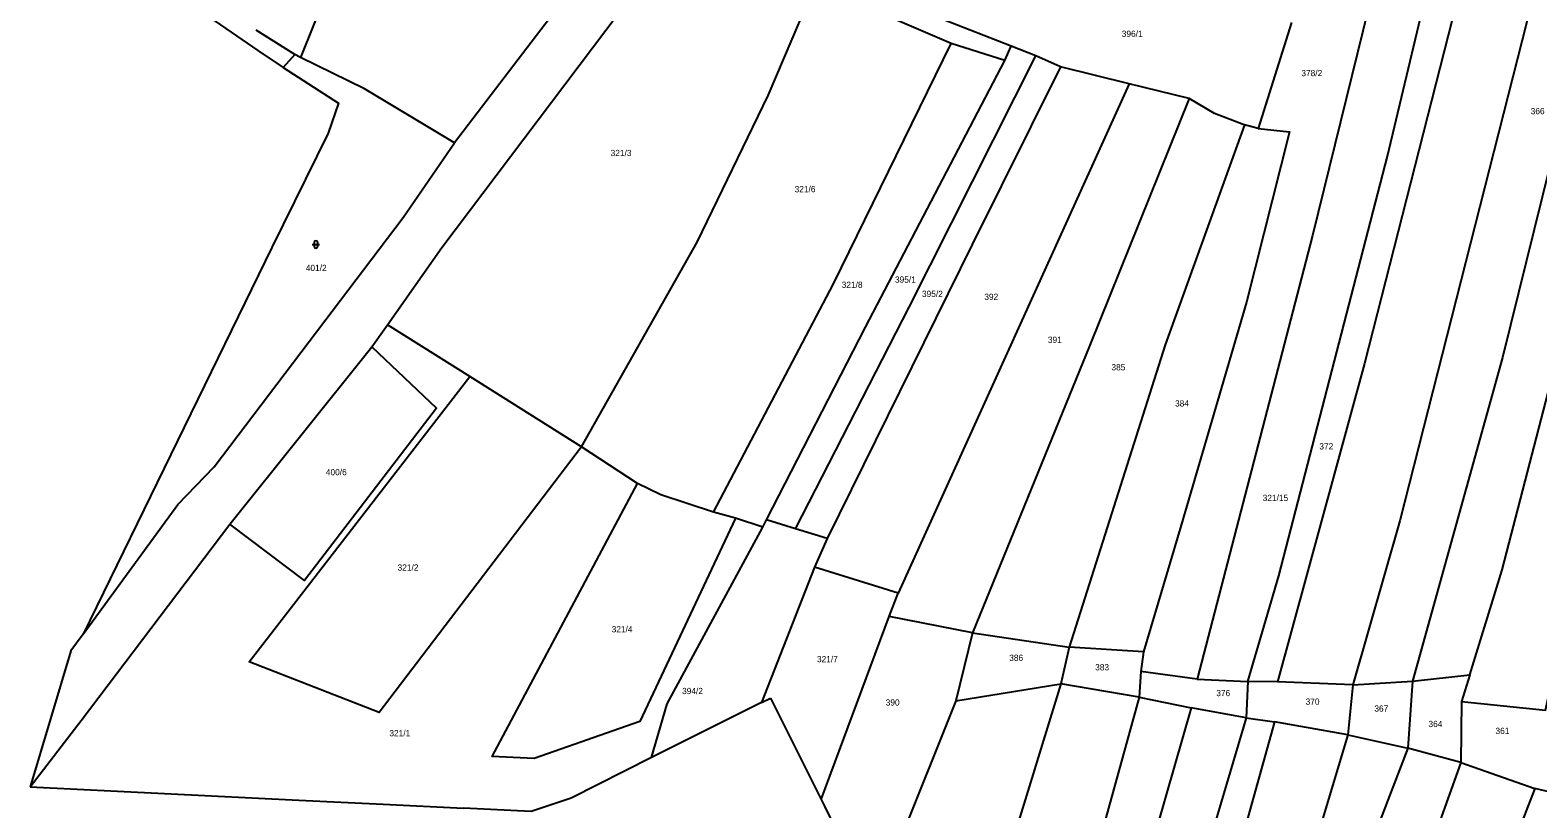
# Model space of a CAD drawing. Extents: x -746176 to -739709, y -1128407 to -1124482.
# Drawn here: x -744013.6 to -743602.7, y -1127772.3 to -1127560 of the extents above; entities that cross this region are included whole.
import ezdxf

# ---------------------------------------------------------------- set-up
doc = ezdxf.new("R2010")
doc.units = 0
for name, color, linetype in [('Vrstva 33', 7, 'Continuous'), ('Vrstva 42', 7, 'Continuous'), ('Vrstva 44', 7, 'Continuous')]:
    doc.layers.add(name, color=color, linetype=linetype)

msp = doc.modelspace()

# ---------------------------------------------------------------- linework, layer by layer
at = {"layer": 'Vrstva 33'}
for p, q in [((-743762.59, -1127563.64), (-743799.59, -1127547.73)), ((-743746.22, -1127564.41), (-743764.87, -1127557.13)), ((-743941.47, -1127566.69), (-743952.02, -1127560)), ((-743669.86, -1127557.99), (-743678.91, -1127586.83)), ((-743951.49, -1127565.55), (-743944.64, -1127570.24)), ((-743747.9, -1127568.32), (-743762.59, -1127563.64)), ((-743747.9, -1127568.32), (-743746.22, -1127564.41)), ((-743739.51, -1127567.07), (-743746.22, -1127564.41)), ((-743941.47, -1127566.69), (-743944.64, -1127570.24)), ((-743939.9, -1127567.46), (-743941.47, -1127566.69)), ((-743732.8, -1127570.06), (-743739.51, -1127567.07)), ((-743714.07, -1127574.65), (-743732.8, -1127570.06)), ((-743714.07, -1127574.65), (-743777.04, -1127713.53)), ((-743697.73, -1127578.65), (-743714.07, -1127574.65)), ((-743678.91, -1127586.83), (-743682.66, -1127585.84)), ((-743947.67, -1127619.31), (-743999.16, -1127724.64)), ((-743920.46, -1127646.39), (-743916.19, -1127640.32)), ((-743893.74, -1127654.46), (-743916.19, -1127640.32)), ((-743959.16, -1127694.66), (-743920.46, -1127646.39)), ((-743863.3, -1127673.64), (-743893.74, -1127654.46)), ((-743848.02, -1127683.56), (-743863.3, -1127673.64)), ((-743821.37, -1127693.07), (-743827.35, -1127691.38)), ((-743813.91, -1127695.5), (-743821.37, -1127693.07)), ((-743813.91, -1127695.5), (-743812.88, -1127693.5)), ((-743804.98, -1127695.97), (-743812.88, -1127693.5)), ((-743796.4, -1127698.58), (-743804.98, -1127695.97)), ((-743796.4, -1127698.58), (-743799.83, -1127706.36)), ((-743799.83, -1127706.36), (-743814.29, -1127743.33)), ((-743777.04, -1127713.53), (-743799.83, -1127706.36)), ((-743779.45, -1127719.83), (-743777.04, -1127713.53)), ((-743798.01, -1127769.73), (-743779.45, -1127719.83)), ((-743756.8, -1127724.26), (-743779.45, -1127719.83)), ((-743999.16, -1127724.64), (-744000.94, -1127727.08)), ((-743756.8, -1127724.26), (-743761.26, -1127742.79)), ((-743756.8, -1127724.26), (-743730.37, -1127728.24)), ((-744002.49, -1127729.2), (-744013.58, -1127766.31)), ((-744000.94, -1127727.08), (-744002.49, -1127729.2)), ((-743730.37, -1127728.24), (-743732.64, -1127738.2)), ((-743710.14, -1127729.48), (-743730.37, -1127728.24)), ((-743710.14, -1127729.48), (-743710.85, -1127734.84)), ((-743732.64, -1127738.2), (-743772.75, -1127867.77)), ((-743761.26, -1127742.79), (-743732.64, -1127738.2)), ((-743711.36, -1127741.87), (-743732.64, -1127738.2)), ((-743710.85, -1127734.84), (-743711.36, -1127741.87)), ((-743695.53, -1127736.94), (-743710.85, -1127734.84)), ((-743695.53, -1127736.94), (-743681.73, -1127737.55)), ((-743681.73, -1127737.55), (-743682.17, -1127747.48)), ((-743673.66, -1127737.68), (-743681.73, -1127737.55)), ((-743653.09, -1127738.43), (-743673.66, -1127737.68)), ((-743653.09, -1127738.43), (-743654.42, -1127752.06)), ((-743653.09, -1127738.43), (-743636.86, -1127737.44)), ((-743636.86, -1127737.44), (-743638.13, -1127755.73)), ((-743636.86, -1127737.44), (-743621.23, -1127735.75)), ((-743621.23, -1127735.75), (-743623.51, -1127743.05)), ((-743814.29, -1127743.33), (-743811.84, -1127742.1)), ((-743811.84, -1127742.1), (-743803.66, -1127758.46)), ((-743711.36, -1127741.87), (-743749.96, -1127881.78)), ((-743711.36, -1127741.87), (-743697.14, -1127744.72)), ((-743814.29, -1127743.33), (-743844.2, -1127758.32)), ((-743761.26, -1127742.79), (-743786, -1127804.52)), ((-743682.17, -1127747.48), (-743697.14, -1127744.72)), ((-743623.51, -1127743.05), (-743623.67, -1127759.6)), ((-743682.17, -1127747.48), (-743674.43, -1127748.6)), ((-743654.42, -1127752.06), (-743674.43, -1127748.6)), ((-743654.42, -1127752.06), (-743638.13, -1127755.73)), ((-743803.66, -1127758.46), (-743798.01, -1127769.73)), ((-743623.67, -1127759.6), (-743638.13, -1127755.73)), ((-743623.67, -1127759.6), (-743603.54, -1127766.74)), ((-744013.58, -1127766.31), (-743940.34, -1127769.88)), ((-743597.33, -1127768.16), (-743603.54, -1127766.74)), ((-743940.34, -1127769.88), (-743917.34, -1127771)), ((-743917.34, -1127771), (-743895.51, -1127772.06)), ((-743798.01, -1127769.73), (-743797.09, -1127771.57))]:
    msp.add_line(p, q, dxfattribs=at)
for points in [[(-743681.73, -1127737.55), (-743673.31, -1127708.75), (-743643.68, -1127594.43), (-743625.08, -1127516.64), (-743598.16, -1127415.52), (-743591.07, -1127395.53)], [(-743583.33, -1127400.78), (-743589.64, -1127417.03), (-743612.49, -1127501.11), (-743625.94, -1127556.86), (-743649.9, -1127650.85), (-743673.66, -1127737.68)], [(-743566.53, -1127412.16), (-743578.37, -1127448.95), (-743606.94, -1127562.76), (-743640.25, -1127693.79), (-743653.09, -1127738.43)], [(-743551.54, -1127422.32), (-743561.28, -1127447), (-743590.72, -1127561.84), (-743612.33, -1127649.25), (-743636.86, -1127737.44)], [(-743621.23, -1127735.75), (-743612.44, -1127707.12), (-743584.91, -1127601.01), (-743579.58, -1127574.43), (-743546.31, -1127450.09), (-743538.8, -1127430.57)], [(-743890.78, -1127464.77), (-743894.21, -1127472.31), (-743932.79, -1127549.82), (-743939.9, -1127567.46)], [(-743829.49, -1127502.59), (-743848.49, -1127526.01), (-743897.9, -1127590.74)], [(-743916.19, -1127640.32), (-743901.38, -1127619.25), (-743849.15, -1127549.98), (-743837.01, -1127534.27), (-743830.84, -1127526.09)], [(-743642.79, -1127529.21), (-743664.09, -1127615.99), (-743695.53, -1127736.94)], [(-743863.3, -1127673.64), (-743831.79, -1127617.79), (-743812.41, -1127577.87), (-743799.59, -1127547.73)], [(-743973.44, -1127552.88), (-743964.58, -1127556.58), (-743951.49, -1127565.55)], [(-743827.35, -1127691.38), (-743794.63, -1127629.19), (-743762.59, -1127563.64)], [(-743897.9, -1127590.74), (-743922.45, -1127576.03), (-743939.9, -1127567.46)], [(-743812.88, -1127693.5), (-743785.95, -1127640.98), (-743747.9, -1127568.32)], [(-743804.98, -1127695.97), (-743774.01, -1127635.57), (-743739.51, -1127567.07)], [(-743732.8, -1127570.06), (-743756.85, -1127618.5), (-743796.4, -1127698.58)], [(-743944.64, -1127570.24), (-743929.53, -1127579.94), (-743932.4, -1127588.16), (-743947.67, -1127619.31)], [(-743697.73, -1127578.65), (-743724.77, -1127645.91), (-743756.8, -1127724.26)], [(-743682.66, -1127585.84), (-743683.02, -1127585.74), (-743690.83, -1127582.75), (-743697.73, -1127578.65)], [(-743682.66, -1127585.84), (-743704.24, -1127645.83), (-743730.37, -1127728.24)], [(-743678.91, -1127586.83), (-743670.32, -1127587.74), (-743682.11, -1127634.16), (-743699.9, -1127694.98), (-743710.14, -1127729.48)], [(-743999.16, -1127724.64), (-743973.35, -1127689.28), (-743963.41, -1127679.08), (-743911.89, -1127611.12), (-743897.9, -1127590.74)], [(-743920.46, -1127646.39), (-743902.84, -1127663.05), (-743938.82, -1127710.08), (-743959.16, -1127694.66)], [(-743863.3, -1127673.64), (-743918.42, -1127746.02), (-743953.89, -1127732.21), (-743893.74, -1127654.46)], [(-743821.37, -1127693.07), (-743847.43, -1127748.51), (-743876.2, -1127758.54), (-743887.66, -1127758.02), (-743848.02, -1127683.56)], [(-743827.35, -1127691.38), (-743841.68, -1127686.73), (-743848.02, -1127683.56)], [(-744013.58, -1127766.31), (-743999.71, -1127748.24), (-743959.16, -1127694.66)], [(-743844.2, -1127758.32), (-743840, -1127743.62), (-743813.91, -1127695.5)], [(-743623.51, -1127743.05), (-743600.59, -1127745.39), (-743599.16, -1127738.75)], [(-743697.14, -1127744.72), (-743722.54, -1127832.92), (-743758.56, -1127965.24), (-743768.26, -1127978.29)], [(-743682.17, -1127747.48), (-743691.92, -1127780.31), (-743702.59, -1127822), (-743742.13, -1127967.1), (-743746.82, -1127980.32), (-743752.61, -1127992.31)], [(-743674.43, -1127748.6), (-743699.34, -1127837.9), (-743736.36, -1127973.94), (-743740.21, -1127984.65), (-743746.7, -1127998.56)], [(-743654.42, -1127752.06), (-743678.95, -1127833.74), (-743701.86, -1127917.81), (-743716.39, -1127977.76), (-743727.47, -1128007.97)], [(-743844.2, -1127758.32), (-743866.16, -1127769.33), (-743877.07, -1127772.96), (-743895.51, -1127772.06)], [(-743638.13, -1127755.73), (-743649.76, -1127786.02), (-743663.84, -1127835.21), (-743701.08, -1127980.88), (-743710.41, -1128008.62)], [(-743623.67, -1127759.6), (-743635.09, -1127791.61), (-743657.85, -1127867.39), (-743686.5, -1127979.4), (-743693.63, -1128000.15)], [(-743603.54, -1127766.74), (-743612.96, -1127791.11), (-743627.05, -1127838.6), (-743649.69, -1127926.04), (-743667.73, -1127984.22)], [(-743797.09, -1127771.57), (-743791.43, -1127782.89), (-743791.23, -1127783.7)]]:
    msp.add_lwpolyline(points, dxfattribs=at)
at = {"layer": 'Vrstva 44'}
for p, q in [((-743936.69, -1127618.45), (-743934.69, -1127618.45)), ((-743936.19, -1127617.95), (-743936.19, -1127618.95)), ((-743935.19, -1127618.95), (-743935.19, -1127617.95))]:
    msp.add_line(p, q, dxfattribs=at)
for centre, start, end in [((-743935.69, -1127617.95), 0, 180), ((-743935.69, -1127618.95), 180, 359.9879)]:
    msp.add_arc(centre, 0.5, start, end, dxfattribs=at)

# ---------------------------------------------------------------- texts
at = {"layer": 'Vrstva 42'}
for s, p in [('396/1', (-743716.08, -1127561.87)), ('378/2', (-743667.13, -1127572.58)), ('366', (-743604.63, -1127582.95)), ('321/3', (-743855.39, -1127594.37)), ('321/6', (-743805.24, -1127604.22)), ('401/2', (-743938.46, -1127625.7)), ('395/1', (-743777.88, -1127628.87)), ('321/8', (-743792.4, -1127630.28)), ('395/2', (-743770.53, -1127632.76)), ('392', (-743753.54, -1127633.56)), ('391', (-743736.21, -1127645.27)), ('385', (-743718.89, -1127652.77)), ('384', (-743701.56, -1127662.61)), ('372', (-743662.23, -1127674.32)), ('400/6', (-743932.99, -1127681.35)), ('321/15', (-743677.68, -1127688.38)), ('321/2', (-743913.44, -1127707.36)), ('321/4', (-743855.1, -1127724.17)), ('386', (-743746.75, -1127731.95)), ('321/7', (-743799.14, -1127732.3)), ('383', (-743723.33, -1127734.53)), ('394/2', (-743835.91, -1127741)), ('390', (-743780.41, -1127744.12)), ('376', (-743690.32, -1127741.56)), ('370', (-743665.97, -1127743.9)), ('367', (-743647.24, -1127745.78)), ('321/1', (-743915.68, -1127752.5)), ('364', (-743632.49, -1127749.99)), ('361', (-743614.23, -1127751.87))]:
    msp.add_text(s, height=1.7, dxfattribs=at).set_placement(p)

doc.saveas('drawing.dxf')
